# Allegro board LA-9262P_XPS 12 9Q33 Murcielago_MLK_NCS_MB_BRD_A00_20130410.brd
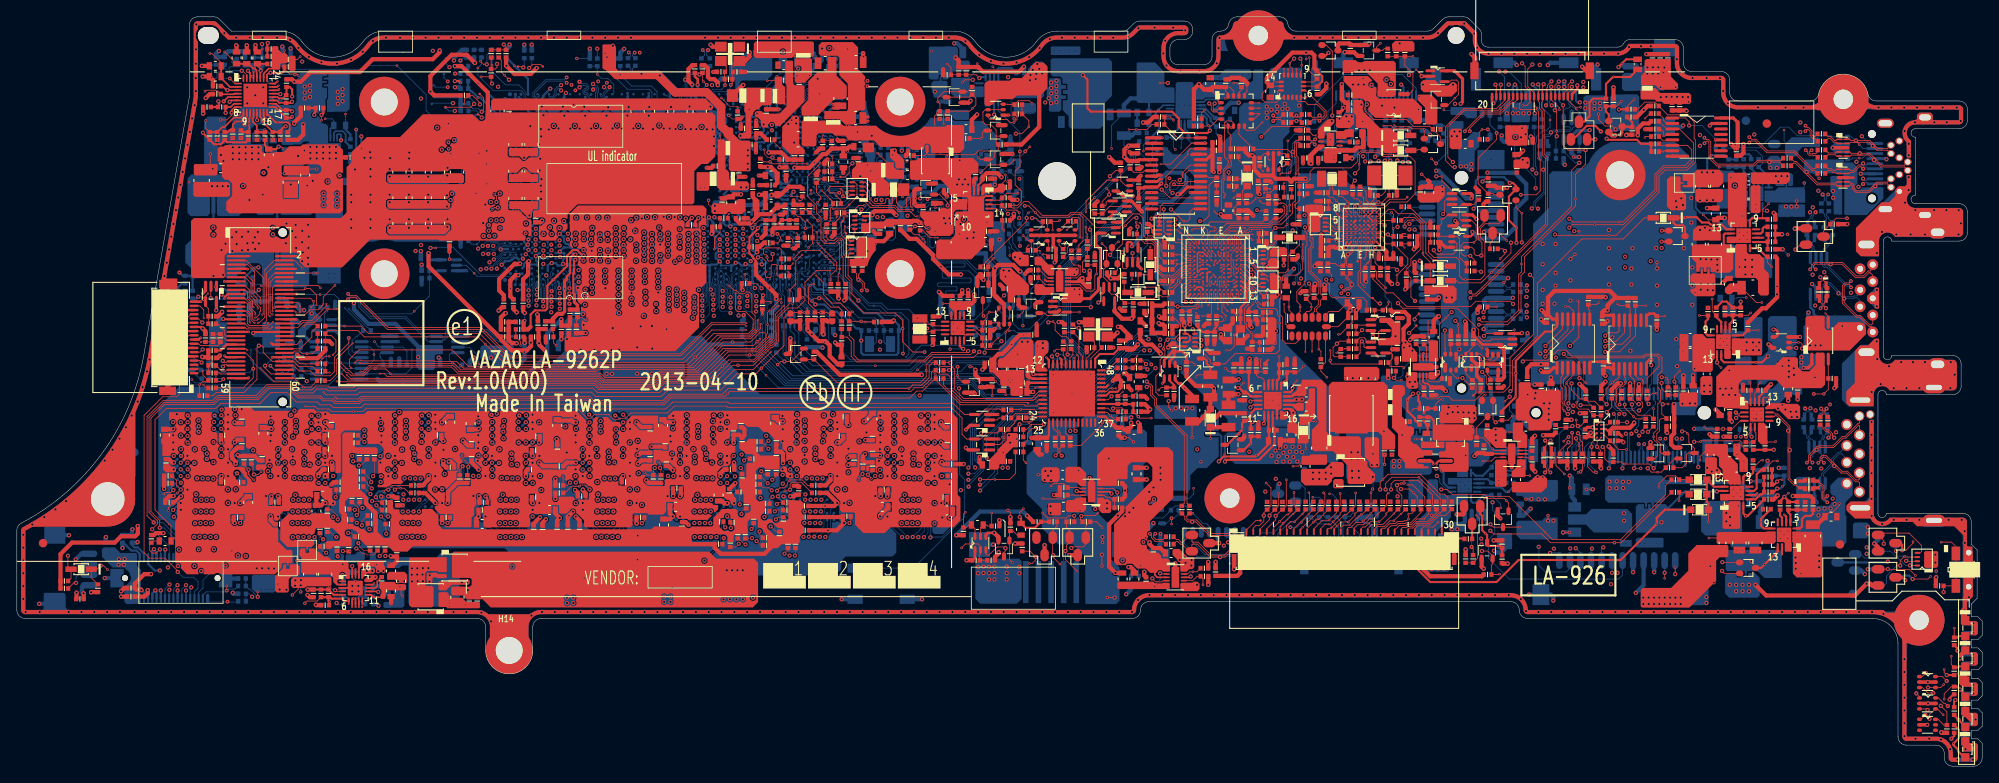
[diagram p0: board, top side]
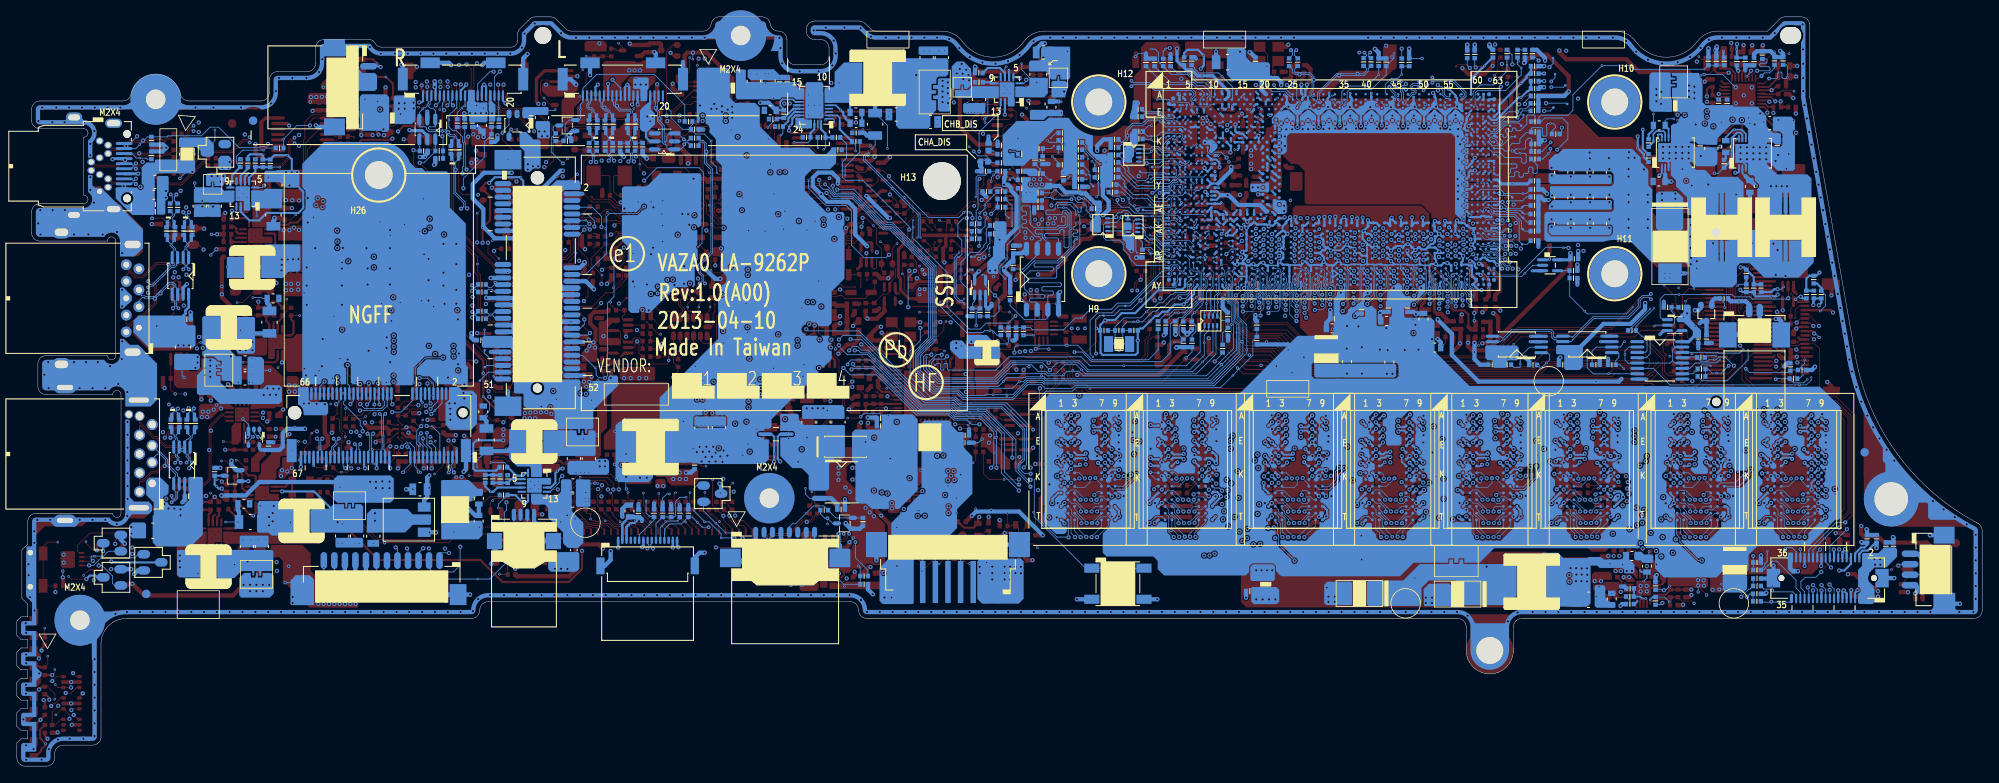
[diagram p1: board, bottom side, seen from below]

Outline 233.5 x 89.05 mm; copper layers: TOP, GND1, IN1, GND2, IN2, GND3, VCC, IN3, GND4, IN4, GND5, BOTTOM. Coordinates in mm from the lower left corner of the outline.
Outline path: 0,28 0,18.55 arc(0.29,17.84) 1,17.55 54.7,17.55 arc(55.41,17.26) 55.7,16.55 55.7,13.75 arc(58.5,10.95) 61.3,13.75 61.3,16.55 arc(61.59,17.26) 62.3,17.55 132.5,17.55 arc(133.21,17.84) 133.5,18.55 arc(133.79,19.26) 134.5,19.55 177.5,19.55 arc(178.21,19.26) 178.5,18.55 arc(178.79,17.84) 179.5,17.55 220.5,17.55 arc(222.62,16.67) 223.5,14.55 223.5,3.5 arc(223.79,2.79) 224.5,2.5 228,2.5 arc(228.71,2.21) 229,1.5 229,1 arc(229.29,0.29) 230,0 232.5,0 arc(233.21,0.29) 233.5,1 233.5,2.75 233,3.25 232.2,3.25 232.2,4.25 233,4.25 233.5,4.75 233.5,6.35 233,6.85 232.2,6.85 232.2,7.85 233,7.85 233.5,8.35 233.5,9.95 233,10.45 232.2,10.45 232.2,11.45 233,11.45 233.5,11.95 233.5,13.55 233,14.05 232.2,14.05 232.2,15.05 233,15.05 233.5,15.55 233.5,17.25 233,17.75 232.2,17.75 232.2,19.25 232.9,19.95 232.9,25.7 232.2,26.4 232.2,29.05 arc(231.91,29.76) 231.2,30.05 222.12,30.05 arc(221.62,29.55) 221.12,30.05 221.12,44.15 arc(221.62,44.65) 222.12,44.15 230,44.15 arc(230.71,44.44) 231,45.15 231,47.8 arc(230.71,48.51) 230,48.8 222.75,48.8 arc(222.25,48.3) 221.75,48.8 221.75,62.4 arc(222.25,62.9) 222.75,62.4 230.75,62.4 arc(231.46,62.69) 231.75,63.4 231.75,65.85 arc(231.46,66.56) 230.75,66.85 225.55,66.85 arc(225.05,67.35) 225.55,67.85 225.55,74.75 arc(225.05,75.25) 225.55,75.75 230.75,75.75 arc(231.46,76.04) 231.75,76.75 231.75,78.05 arc(231.46,78.76) 230.75,79.05 220.92,79.05 arc(220.29,79.28) 219.94,79.85 arc(217,82.25) 214.06,79.85 arc(213.71,79.28) 213.08,79.05 204.5,79.05 arc(203.79,79.34) 203.5,80.05 203.5,81.55 arc(203.21,82.26) 202.5,82.55 199,82.55 arc(198.29,82.84) 198,83.55 198,85.35 arc(197.71,86.06) 197,86.35 191.64,86.35 arc(191.21,86.23) 190.92,85.9 arc(190.62,85.57) 190.2,85.45 174.8,85.45 arc(174.23,85.68) 174,86.25 174,87.02 arc(173.94,87.32) 173.77,87.58 172.59,88.76 arc(172.27,88.97) 171.89,89.05 170.11,89.05 arc(169.73,88.97) 169.41,88.76 168.29,87.64 arc(167.97,87.43) 167.59,87.35 152,87.35 arc(151.35,87.59) 151.01,88.2 arc(150.67,88.81) 150.02,89.05 144.98,89.05 arc(144.33,88.81) 143.99,88.2 arc(143.65,87.59) 143,87.35 arc(142.29,87.06) 142,86.35 142,84.35 arc(141.71,83.64) 141,83.35 138,83.35 arc(137.29,83.64) 137,84.35 137,85.35 arc(137.29,86.06) 138,86.35 138.7,86.35 arc(139.41,86.64) 139.7,87.35 139.7,87.55 arc(139.41,88.26) 138.7,88.55 133.41,88.55 arc(133.03,88.47) 132.71,88.26 132.09,87.64 arc(131.77,87.43) 131.39,87.35 123.57,87.35 arc(122.21,87.02) 121.14,86.11 arc(117.5,84.25) 113.86,86.11 arc(112.79,87.02) 111.43,87.35 43.57,87.35 arc(42.21,87.02) 41.14,86.11 arc(37.5,84.25) 33.86,86.11 arc(32.79,87.02) 31.43,87.35 25.5,87.35 24.09,88.76 arc(23.77,88.97) 23.39,89.05 21.5,89.05 arc(20.79,88.76) 20.5,88.05 20.5,79.55 15.07,48.8 arc(10.11,37.15) 0.53,28.88 arc(0.14,28.52) 0,28

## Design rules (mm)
constraint set DEFAULT: min track width 0.102
net group BUS_RTC: nets PCH_RTCRST# PCH_SRTCRST#
net group BUS_SPI-CLK-15: nets PCH_SPI_CLK SPI_CLK_ROM
net group DIFFPAIR0: nets CLK_PCIE2 CLK_PCIE2#
net group DP-BQTMAN: nets BATMAN_CLK BATMAN_DATA
net group DP_ALS-SMB: nets ALS_SMBCLK ALS_SMBDATA
net group DP_SML0: nets SML0CLK SML0DATA
net group EDP_AUXP_C: nets EDP_AUXN_C EDP_AUXP_C
net group EDP_TXN_P1_C: nets EDP_TXN_P1_C EDP_TXP_P1_C
net group EDP_TXP_P0_C: nets EDP_TXN_P0_C EDP_TXP_P0_C
net group H_CPU_SVIDALRT#: nets H_CPU_SVIDALRT# VR_SVID_ALRT#
net group H_CPU_SVIDCLK: nets H_CPU_SVIDCLK VR_SVID_CLK
net group H_CPU_SVIDDAT: nets H_CPU_SVIDDAT VR_SVID_DAT
net group PCH_DP_AUXN: nets PCH_DP_AUXN PCH_DP_AUXN_C
net group PCH_DP_AUXP: nets PCH_DP_AUXP PCH_DP_AUXP_C
net group PCIE_PTX_DRX_N4: nets PCIE_PTX_DRX_N4 PCIE_PTX_DRX_N4_C
net group PCIE_PTX_DRX_P4: nets PCIE_PTX_DRX_P4 PCIE_PTX_DRX_P4_C
net group SATA_PRX_DTX_N0: nets SATA_PRX_DTX_N0 SATA_PRX_DTX_N0_C
net group SATA_PRX_DTX_P0: nets SATA_PRX_DTX_P0 SATA_PRX_DTX_P0_C
net group SATA_PTX_DRX_N0: nets SATA_PTX_DRX_N0 SATA_PTX_DRX_N0_C
net group SATA_PTX_DRX_P0: nets SATA_PTX_DRX_P0 SATA_PTX_DRX_P0_C
net group SPACING-15: nets PCH_RTCX1 PCH_RTCX2
net group +1.8VS: nets +1.8VS SDIO_RST# SDIO_WAKE#_Q
net group BUS_ASYNCHRONOUS: nets H_CATERR# H_DRAMRST# H_PECI H_PROCHOT# H_PROCHOT#_R H_THERMTRIP# H_THERMTRIP#_R PCH_PLTRST# VCCSTPG_MCP
net group BUS_CLK: nets CLK_LPC_DEBUG CLK_PCI_LPC CLK_PCI_TPM CLKOUT_LPC0 CLKOUT_LPC1
net group BUS_DDRA_CTL: nets M_ODT0
net group BUS_DDRB_CTL: nets M_ODT2
net group BUS_I2C: nets I2C0_SCK I2C0_SDA I2C1_SCK I2C1_SDA SENSOR_I2C_SCL SENSOR_I2C_SDA
net group BUS_IHDA-CLK: nets HDA_BIT_CLK HDA_BITCLK_AUDIO HDA_BITCLK_AUDIO_C HDA_BITCLK_DSP
net group BUS_IHDA-DATA: nets HDA_RST# HDA_RST_AUDIO# HDA_RST_DSP# HDA_SDIN0 HDA_SDIN0_AUDIO HDA_SDIN0_DSP HDA_SDOUT HDA_SDOUT_AUDIO HDA_SDOUT_DSP HDA_SPKR HDA_SYNC HDA_SYNC_AUDIO HDA_SYNC_DSP
net group BUS_LPC: nets LPC_AD0 LPC_AD1 LPC_AD2 LPC_AD3 LPC_FRAME#
net group BUS_POWER-RAIL: nets +1.2V_TON BOOT_+1.2V BST_+1.05VS CHG_LGATE CHG_UGATE CPU_B+ DH_+1.2V DL_+1.2V P1 PWM1 PWM2 SKIP# SKIP#1 SKIP#2 SNUB_1.5VSP SNUB_+1.2V SNUB_+1.05V SNUB_CHG SNUB_PHASE1 SNUB_PHASE2 SW_+1.2V SW_+1.05VS
net group BUS_SPI: nets PCH_SPI_CS# PCH_SPI_IO2 PCH_SPI_IO3 PCH_SPI_SI PCH_SPI_SO SPI_IO2_ROM SPI_IO3_ROM SPI_SI_ROM SPI_SO_ROM TPM_IRQ#
net group BUS_UART1: nets UART1_CTS# UART1_CTS#_NGFF UART1_RTS# UART1_RTS#_NGFF UART1_RXD UART1_RXD_NGFF UART1_TXD UART1_TXD_NGFF
net group BUS_USB2.0: nets SW_USB20_N1 SW_USB20_P1 USB20_N1 USB20_N2_R USB20_P1 USB20_P2_R
net group BUS_USB3.0: nets USB3TN0_C USB3TN1_C USB3TP0_C USB3TP1_C
net group DP_PCH-SML: nets PCH_SMLDATA
net group I2S_BCLK_OUT: nets I2S_BCLK_OUT I2S_CLK I2S_CLK_IN I2S_SFRM_IN
net group IHDA_DATA-5_10: nets HDA_SDO
net group PCH_DP_N0: nets PCH_DP_N0
net group PCH_DP_N1: nets PCH_DP_N1
net group PCH_DP_N2: nets PCH_DP_N2
net group PCH_DP_N3: nets PCH_DP_N3
net group PCH_DP_P0: nets PCH_DP_P0
net group PCH_DP_P1: nets PCH_DP_P1
net group PCH_DP_P2: nets PCH_DP_P2
net group PCH_DP_P3: nets PCH_DP_P3
net group R_DDRA-D0: nets DDR_A_D0 DDR_A_D1 DDR_A_D2 DDR_A_D3 DDR_A_D4 DDR_A_D5 DDR_A_D6 DDR_A_D7 DDR_A_DQS0 DDR_A_DQS#0
net group R_DDRA-D1: nets DDR_A_D8 DDR_A_D9 DDR_A_D10 DDR_A_D11 DDR_A_D12 DDR_A_D13 DDR_A_D14 DDR_A_D15 DDR_A_DQS1 DDR_A_DQS#1
net group R_DDRA-D2: nets DDR_A_D16 DDR_A_D17 DDR_A_D18 DDR_A_D19 DDR_A_D20 DDR_A_D21 DDR_A_D22 DDR_A_D23 DDR_A_DQS2 DDR_A_DQS#2
net group R_DDRA-D3: nets DDR_A_D24 DDR_A_D25 DDR_A_D26 DDR_A_D27 DDR_A_D28 DDR_A_D29 DDR_A_D30 DDR_A_D31 DDR_A_DQS3 DDR_A_DQS#3
net group R_DDRA-D4: nets DDR_A_D32 DDR_A_D33 DDR_A_D34 DDR_A_D35 DDR_A_D36 DDR_A_D37 DDR_A_D38 DDR_A_D39 DDR_A_DQS4 DDR_A_DQS#4
net group R_DDRA-D5: nets DDR_A_D40 DDR_A_D41 DDR_A_D42 DDR_A_D43 DDR_A_D44 DDR_A_D45 DDR_A_D46 DDR_A_D47 DDR_A_DQS5 DDR_A_DQS#5
net group R_DDRA-D6: nets DDR_A_D48 DDR_A_D49 DDR_A_D50 DDR_A_D51 DDR_A_D52 DDR_A_D53 DDR_A_D54 DDR_A_D55 DDR_A_DQS6 DDR_A_DQS#6
net group R_DDRA-D7: nets DDR_A_D56 DDR_A_D57 DDR_A_D58 DDR_A_D59 DDR_A_D60 DDR_A_D61 DDR_A_D62 DDR_A_D63 DDR_A_DQS7 DDR_A_DQS#7
net group R_DDRB-D0: nets DDR_B_D0 DDR_B_D1 DDR_B_D2 DDR_B_D3 DDR_B_D4 DDR_B_D5 DDR_B_D6 DDR_B_D7 DDR_B_DQS0 DDR_B_DQS#0
net group R_DDRB-D1: nets DDR_B_D8 DDR_B_D9 DDR_B_D10 DDR_B_D11 DDR_B_D12 DDR_B_D13 DDR_B_D14 DDR_B_D15 DDR_B_DQS1 DDR_B_DQS#1
net group R_DDRB-D2: nets DDR_B_D16 DDR_B_D17 DDR_B_D18 DDR_B_D19 DDR_B_D20 DDR_B_D21 DDR_B_D22 DDR_B_D23 DDR_B_DQS2 DDR_B_DQS#2
net group R_DDRB-D3: nets DDR_B_D24 DDR_B_D25 DDR_B_D26 DDR_B_D27 DDR_B_D28 DDR_B_D29 DDR_B_D30 DDR_B_D31 DDR_B_DQS3 DDR_B_DQS#3
net group R_DDRB-D4: nets DDR_B_D32 DDR_B_D33 DDR_B_D34 DDR_B_D35 DDR_B_D36 DDR_B_D37 DDR_B_D38 DDR_B_D39 DDR_B_DQS4 DDR_B_DQS#4
net group R_DDRB-D5: nets DDR_B_D40 DDR_B_D41 DDR_B_D42 DDR_B_D43 DDR_B_D44 DDR_B_D45 DDR_B_D46 DDR_B_D47 DDR_B_DQS5 DDR_B_DQS#5
net group R_DDRB-D6: nets DDR_B_D48 DDR_B_D49 DDR_B_D50 DDR_B_D51 DDR_B_D52 DDR_B_D53 DDR_B_D54 DDR_B_D55 DDR_B_DQS6 DDR_B_DQS#6
net group R_DDRB-D7: nets DDR_B_D56 DDR_B_D57 DDR_B_D58 DDR_B_D59 DDR_B_D60 DDR_B_D61 DDR_B_D62 DDR_B_D63 DDR_B_DQS7 DDR_B_DQS#7
nets with their own width: min track width 0.254; nets +VCCIO_OUT AOAC_THERMAL ECAGND LP# SATA_RCOMP VCCSENSE VCCSENSE_R VCIN0_PH VSSSENSE
nets with their own width: min track width 0.305; nets PCH_OPIRCOMP PCIE_RCOMP PROC_OPI_COMP
nets with their own width: min track width 0.381; nets +3VS_CAM +V1.05S_ASATA3PLL CFG_RCOMP SM_RCOMP0 SM_RCOMP1 SM_RCOMP2
nets with their own width: min track width 0.508; nets 1.2_PGND +0.6VSP +1.2V_B+ +1.2V_FB +1.2VP +1.2VS_DVDD +1.05VA +1.05VS +1.5VS +1.05VS_B+ +1.5VS_D +1.05VS_VCCST +1.05VS_XDP +1.05VSP +1.5VSP +3V_D +3V_PCH +3V_PCH_DSW +3VALW +3VALW_EC +3VLP +3VNS_PWR +3VS +3VS_AUDIO +5VS +5VS_AUDIO +5VS_KBL +EC_VCCA +EDP_COM +INV_PWR_SRC +LCDVDD +LCDVDD_R +PCH_VCCDSW +RTC_VCCSUS +RTCBATT +RTCVCC +V1.05A_AOSCSUS +V1.05S_APLLOPI +V1.05S_AUSB3PLL +V1.05S_AXCK_DCB +V1.05S_AXCK_LCPLL +V18R +VCC_CORE +VCCIOA_OUT +VCCP_D +VCHGR +VREFCA +VREFDQ_A +VREFDQ_B +VS_LPSS_SDIO B+ GND N88620271 N90173610 V_DDR_REF_CA V_DDR_REFA_R V_DDR_REFB_R VCC
nets with their own width: min track width 1.016; nets +3.3VDX_SSD
nets with their own width: min track width 2.032; nets +5V_USB_P0 +5V_USB_P1

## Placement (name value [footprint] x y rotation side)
C265  -  [C_0402]  212.63 32.09 0 bottom
C276  -  [C_0402]  136.38 51.4 0 top
C277  -  [C_0402]  136.38 52.29 0 top
C278  -  [C_0402]  148.98 51.27 180 top
C279  -  [C_0402]  148.98 52.16 180 top
C280  -  [C_0402]  133.97 54.06 0 top
C281  -  [C_0402]  133.97 54.95 0 top
C282  -  [C_0402]  144.46 53.17 0 top
C283  -  [C_0402]  147.68 49.49 0 top
C285  -  [C_0402]  139.32 54.07 270 top
C286  -  [C_0402]  145.39 54.06 180 top
C293  -  [C_0603]  143.95 65.3 90 top
C303  -  [C_1206]  216.03 27.98 0 bottom
C352  -  [C_0402]  118.12 56.73 180 top
C355  -  [C_0402]  121.36 58.06 180 top
C612  -  [C_0402]  159.07 79.77 180 top
C613  -  [C_0402]  163.89 85.27 270 top
C617  -  [C_0402]  178.21 71.46 270 top
C621  -  [C_0402]  214.26 40.59 90 top
C623  -  [C_0402]  215.15 40.59 90 top
C655  -  [C_0402]  142.87 71.22 90 top
C656  -  [C_0402]  32.53 83.31 90 bottom
C712  -  [C_0603]  182.26 44.07 90 top
C713  -  [C_0402]  198 44.12 90 top
C715  -  [C_0402]  181.12 44.44 90 top
C716  -  [C_0603]  199.16 43.81 90 top
C719  -  [C_0603]  167.81 67.48 90 top
C720  -  [C_0402]  166.73 67.78 90 top
C721  -  [C_0402]  167.56 56.38 270 top
C722  -  [C_0402]  177.92 50.63 0 bottom
C962  -  [C_0603]  202.37 43.08 270 top
C963  -  [C_0402]  203.51 42.84 270 top
C964  -  [C_0402]  154.93 48.36 270 top
C965  -  [C_0603]  158.07 55.05 0 top
C966  -  [C_0402]  158.19 53.28 0 top
C968  -  [C_0603]  150.81 55.65 90 top
C969  -  [C_0603]  141.79 80.42 90 top
C970  -  [C_0402]  143.62 80.7 90 top
C974  -  [C_0402]  145.5 80.7 90 top
C976  -  [C_0402]  155.84 61.56 180 top
C977  -  [C_0402]  162.72 60.32 180 top
C978  -  [C_0402]  155.84 60.67 180 top
C979  -  [C_0402]  163.55 60.3 0 top
C1059  -  [C_0603]  178.63 28.41 90 bottom
C1060  -  [C_0402]  163.6 73.14 90 bottom
C1061  -  [C_0402]  165.5 73.14 90 bottom
C1062  -  [C_0402]  162.71 73.14 90 bottom
C1063  -  [C_0402]  164.61 73.14 90 bottom
C1064  -  [C_0402]  160.93 73.14 90 bottom
C1065  -  [C_0402]  160.04 73.14 90 bottom
C1078  -  [C_0402]  163.17 30.52 90 top
C1098  -  [C_0402]  13.11 21.17 0 top
C1099  -  [C_0402]  11.43 26.59 270 bottom
C1100  -  [C_0402]  13.09 20.15 0 top
C1101  -  [C_0402]  13.68 27.47 270 bottom
C1102  -  [C_0402]  7.04 19.88 0 top
C1107  -  [C_0402]  214.4 66.87 270 bottom
C1108  -  [C_0402]  215.28 66.87 270 bottom
C1109  -  [C_1206]  213.76 51.12 270 bottom
C1110  -  [C_0402]  213.75 53.11 180 bottom
C1116  -  [C_0402]  136.36 54.06 0 top
C1117  -  [C_0402]  149.61 65.1 90 top
C1118  -  [C_0402]  151.57 61.14 270 top
C1122  -  [C_0402]  228.91 21.42 180 top
C1123  -  [C_0402]  27.22 20.49 180 bottom
C1124  -  [C_0402]  27.2 22.3 180 bottom
C1125  -  [C_0402]  27.2 24.21 180 bottom
C1134  -  [C_0402]  159.65 29.59 90 bottom
C1135  -  [C_0402]  133.28 68.72 90 top
C1136  -  [C_0402]  133.15 71.92 270 top
C1137  -  [C_0402]  142.06 74.13 0 top
C1138  -  [C_0402]  142.06 73.19 0 top
C1139  -  [C_0402]  133.28 67.48 270 top
C1140  -  [C_0402]  133.19 73.74 270 top
C1142  -  [C_0402]  177.11 75.1 270 bottom
C1143  -  [C_0603]  178.24 76.86 270 bottom
C1145  -  [C_0402]  179.38 76.87 270 bottom
C1146  -  [C_0402]  10.54 26.59 270 bottom
C1148  -  [C_0603]  148.91 80.9 270 top
C1149  -  [C_0402]  154.48 80.76 270 top
C1152  -  [C_0402]  152.33 65.32 270 top
C1153  -  [C_0603]  178.61 32.54 270 bottom
C1158  -  [C_0402]  179.18 74.13 0 top
C1159  -  [C_0603]  178.11 74.07 270 top
C1160  -  [C_0402]  176.46 25.06 270 top
C1161  -  [C_0402]  135.03 25.01 90 top
C1162  -  [C_0603]  137.85 25.32 180 top
C1163  -  [C_0402]  140.63 23.52 0 top
C1172  -  [C_0603]  210.46 45.57 270 top
C1173  -  [C_0402]  211.58 45.15 270 top
C1174  -  [C_0402]  166.83 30.52 90 top
C1175  -  [C_0402]  165.92 30.52 90 top
C1176  -  [C_0402]  165 30.52 90 top
C1177  -  [C_0402]  164.09 30.52 90 top
C1178  -  [C_0402]  170.49 30.54 90 top
C1179  -  [C_0402]  169.57 30.54 90 top
C1180  -  [C_0402]  168.66 30.52 90 top
C1181  -  [C_0402]  167.75 30.52 90 top
C1182  -  [C_0402]  158.6 30.52 90 top
C1183  -  [C_0402]  157.69 30.52 90 top
C1184  -  [C_0402]  156.77 30.52 90 top
C1185  -  [C_0402]  155.86 30.52 90 top
C1186  -  [C_0402]  151.29 30.49 90 top
C1187  -  [C_0402]  150.37 30.49 90 top
C1188  -  [C_0402]  149.46 30.49 90 top
C1189  -  [C_0402]  148.54 30.49 90 top
C1190  -  [C_0402]  154.94 30.52 90 top
C1191  -  [C_0402]  154.03 30.52 90 top
C1192  -  [C_0402]  153.12 30.52 90 top
C1193  -  [C_0402]  152.2 30.49 90 top
C1194  -  [C_0402]  162.26 30.52 90 top
C1195  -  [C_0402]  161.35 30.52 90 top
C1196  -  [C_0402]  160.43 30.52 90 top
C1197  -  [C_0402]  159.52 30.52 90 top
C1199  -  [C_0402]  127.31 56.97 90 top
C1200  -  [C_0402]  157.06 76.78 90 top
C1202  -  [C_0402]  180.03 37.48 90 top
C1203  -  [C_0402]  174.31 37.22 90 top
C1204  -  [C_0402]  163.03 67.83 0 top
C1205  -  [C_0402]  161.7 67.83 180 top
C1209  -  [C_0603]  112.06 75.69 0 top
C1212  -  [C_0402]  124.85 32.22 180 top
C1213  -  [C_0402]  130.41 33.62 0 top
C1214  -  [C_0402]  124.85 33.11 180 top
C1215  -  [C_0402]  179.45 45.35 90 top
C1219  -  [C_0402]  174.7 39.59 90 top
C1225  -  [C_0402]  142.42 22.62 90 top
C1227  -  [C_0402]  106.57 72.57 180 top
C1228  -  [C_0402]  113.9 70.75 270 top
C1230  -  [C_0402]  173.81 74.49 0 top
C1231  -  [C_0603]  171.37 73.96 0 top
C1237  -  [C_0402]  35.74 50.52 0 top
C1240  -  [C_0603]  109.05 65.49 90 top
C1241  -  [C_0402]  114.76 69.81 0 top
C1242  -  [C_0402]  117.08 68.8 0 top
C1243  -  [C_0402]  111.07 68.41 180 top
C1244  -  [C_0402]  117.08 67.55 0 top
C1246  -  [C_0402]  167.94 62.26 0 top
C1248  -  [C_0402]  167.19 50.13 90 top
C1254  -  [C_0402]  168.08 45 270 top
C1256  -  [C_0402]  164.85 48.41 180 top
C1257  -  [C_0402]  166.24 50.18 90 top
C1259  -  [C_0402]  175.97 45.89 270 top
C1260  -  [C_0402]  173.93 45.89 270 top
C1261  -  [C_0402]  164.03 50.46 270 top
C1262  -  [C_0402]  164.03 52.34 90 top
C1278  -  [C_0402]  121.36 58.95 180 top
C1279  -  [C_0402]  12.55 26.56 90 bottom
C1280  -  [C_0402]  134.17 22.44 270 top
C1281  -  [C_0402]  140.65 22.57 0 top
C1282  -  [C_0402]  22.8 47 90 bottom
C1283  -  [C_0402]  189.3 39.56 0 top
C1284  -  [C_0402]  186.33 39.1 90 top
C1285  -  [C_0402]  188.36 53.48 270 top
C1286  -  [C_0402]  188.49 47.1 90 top
C1287  -  [C_0402]  181.76 53.61 270 top
C1288  -  [C_0402]  181.76 46.85 90 top
C1289  -  [C_0402]  203.6 37.58 90 bottom
C1292  -  [C_0402]  180.02 36.61 270 top
C1294  -  [C_0402]  111.12 54.97 90 top
C1295  -  [C_0402]  108.85 52.53 90 top
C1296  -  [C_0402]  108.86 51.63 270 top
C1297  -  [C_0402]  158.39 74.18 0 top
C1298  -  [C_0402]  155.53 72.24 180 top
C1299  -  [C_0402]  153.73 72.29 180 top
C1300  -  [C_0402]  128.07 59.58 90 top
CA1  -  [C_0603]  132.01 39.97 0 top
CA2  -  [C_0603]  132.14 49.56 90 top
CA3  -  [C_0603]  121.22 39.01 270 top
CA4  -  [C_0402]  130.99 49.67 90 top
CA5  -  [C_0402]  122.36 39.03 270 top
CA6  -  [C_0402]  130.92 40.22 270 top
CA7  -  [C_0603]  130.82 46.19 0 top
CA8  -  [C_0603]  120.01 44.48 180 top
CA9  -  [C_0603]  116.11 35.8 180 top
CA10  -  [C_0402]  120.15 45.55 180 top
CA11  -  [C_0402]  131.12 45.11 0 top
CA12  -  [C_0402]  117.1 36.22 0 top
CA13  -  [C_0402]  130.8 43.98 270 top
CA14  -  [C_0402]  132.63 43.97 0 top
CA15  -  [C_0402]  132.65 43.01 0 top
CA16  -  [C_0402]  128.02 49.75 180 top
CA17  -  [C_0402]  128.89 49.75 0 top
CA18  -  [C_0402]  119.37 47.73 270 top
CA19  -  [C_0603]  118.29 47.9 270 top
CA20  -  [C_0603]  117.02 47.9 270 top
CA21  -  [C_0603]  133.29 44.98 90 top
CA22  -  [C_0603]  133.03 35.46 270 top
CC160  -  [C_0603]  65.73 49.75 180 bottom
CC161  -  [C_0603]  66.36 52.41 90 bottom
CC162  -  [C_0603]  75.48 48.79 270 bottom
CC163  -  [C_0603]  70.05 52.92 0 bottom
CC164  -  [C_0603]  76.52 52.03 0 bottom
CC165  -  [C_0603]  70.43 48.73 270 bottom
CC233  -  [C_0402]  73.73 54.7 270 bottom
CC234  -  [C_0402]  68.27 54.9 270 bottom
CC238  -  [C_0402]  70.56 54.9 270 bottom
CC239  -  [C_0402]  76.52 53.17 0 bottom
CC240  -  [C_0402]  48.91 60.29 180 bottom
CD1  -  [C_0402]  18.55 31.33 180 top
CD2  -  [C_0402]  31.12 31.33 180 top
CD3  -  [C_0402]  26.74 38.77 270 top
CD4  -  [C_0402]  36.56 35.27 0 top
CD5  -  [C_0402]  26.68 29.55 180 top
CD14  -  [C_0402]  26.73 41.69 270 top
CD15  -  [C_0402]  25.15 39.33 180 top
CD16  -  [C_0402]  25.15 33.74 180 top
CD17  -  [C_0402]  37.47 39.33 180 top
CD18  -  [C_0402]  37.47 37.68 180 top
CD19  -  [C_0402]  37.4 41.31 270 top
CD20  -  [C_0603]  27.49 30.63 90 top
CD21  -  [C_0603]  37.05 32.14 180 top
CD22  -  [C_B2]  29.39 24.7 90 bottom
CD23  -  [C_0402]  49.37 47.71 0 bottom
CD24  -  [C_0402]  45.19 31.92 270 top
CD25  -  [C_0402]  55.89 31.33 180 top
CD26  -  [C_0402]  51.04 35.52 0 top
CD27  -  [C_0402]  64.9 35.65 180 top
CD28  -  [C_0402]  51.45 29.55 180 top
CD37  -  [C_0402]  61.6 35.27 180 top
CD38  -  [C_0402]  54.03 37.25 270 top
CD39  -  [C_0402]  55.76 30.44 180 top
CD40  -  [C_0402]  62.11 37.55 180 top
CD41  -  [C_0402]  61.2 39.2 0 top
CD42  -  [C_0402]  62.11 31.97 180 top
CD43  -  [C_0603]  56 28.79 180 top
CD44  -  [C_0603]  62.58 30.44 0 top
CD45  -  [C_0402]  78.87 32.98 180 top
CD46  -  [C_0402]  67.57 32.09 180 top
CD47  -  [C_0402]  75.24 37.25 270 top
CD48  -  [C_0402]  84.31 35.27 0 top
CD49  -  [C_0402]  74.56 29.55 180 top
CD58  -  [C_0402]  77.03 38.77 270 top
CD59  -  [C_0402]  77.15 36.61 270 top
CD60  -  [C_0402]  75.24 39.38 90 top
CD61  -  [C_0402]  86.04 41.19 270 top
CD62  -  [C_0402]  85.15 40.3 270 top
CD63  -  [C_0402]  84.64 32.02 90 top
CD64  -  [C_0603]  83.37 32.92 270 top
CD65  -  [C_0603]  78.99 30.82 180 top
CD66  -  [C_B2]  77.92 49.85 90 bottom
CD67  -  [C_0402]  57.75 47.71 0 bottom
CD68  -  [C_0402]  92.89 32.27 90 top
CD69  -  [C_0402]  103.51 32.85 180 top
CD70  -  [C_0402]  99.47 36.82 270 top
CD71  -  [C_0402]  111.51 35.9 180 top
CD72  -  [C_0402]  99.07 29.68 180 top
CD81  -  [C_0402]  97.26 39.2 0 top
CD82  -  [C_0402]  97.71 41.54 0 top
CD83  -  [C_0402]  101.66 37.88 270 top
CD84  -  [C_0402]  110.55 41.19 270 top
CD85  -  [C_0402]  110.55 38.9 270 top
CD86  -  [C_0402]  109.58 31.97 0 top
CD87  -  [C_0603]  102.1 30.82 0 top
CD88  -  [C_0603]  109.79 30.39 0 top
CD89  -  [C_0402]  60.21 51.9 180 top
CD90  -  [C_0402]  58.43 51.9 180 top
CD91  -  [C_0402]  66.61 54.27 270 top
CD92  -  [C_0402]  63.68 52.87 270 top
CD93  -  [C_0402]  79.05 28.08 90 top
CD94  -  [C_0402]  93.2 28.03 0 top
CD95  -  [C_0402]  93.12 30.92 0 top
CD96  -  [C_0402]  66.86 27.7 90 top
CD97  -  [C_0402]  90.23 36.46 90 top
CD98  -  [C_0402]  86.16 38.11 90 top
CD101  -  [C_0603]  35.59 29.62 90 top
CD102  -  [C_0402]  38.87 33.74 180 top
CD103  -  [C_0402]  64.19 27.7 90 top
CD104  -  [C_0402]  31.68 28.77 180 top
CD105  -  [C_0402]  45.14 25.82 270 top
CD106  -  [C_0402]  65.46 27.7 90 top
CD107  -  [C_0402]  61.4 27.7 90 top
CD110  -  [C_0603]  76.89 27.97 90 top
CD111  -  [C_0402]  72.78 33.74 180 top
CD112  -  [C_0402]  101.66 39.66 270 top
CD113  -  [C_0603]  101.66 40.54 90 top
CD114  -  [C_0603]  90.1 40.03 90 top
CD115  -  [C_0402]  90.24 39.13 270 top
CD116  -  [C_0402]  64.21 37.22 90 top
CD117  -  [C_0603]  76.77 39.78 90 top
CD118  -  [C_0603]  64.21 39.78 90 top
CD119  -  [C_0402]  49.51 39.33 0 top
CD120  -  [C_0402]  54.03 39.03 270 top
CD121  -  [C_0603]  51.49 40.16 90 top
CD122  -  [C_0603]  53.91 41.43 270 top
CD123  -  [C_0402]  29.15 37.25 270 top
CD124  -  [C_0402]  17.71 35.57 90 top
CD125  -  [C_0603]  29.29 38.84 90 top
CD126  -  [C_0603]  17.58 38.63 90 top
CH1  -  [C_0402]  22.75 48.51 0 top
CH2  -  [C_0402]  103.88 51.78 0 bottom
CH3  -  [C_0402]  101.24 51.78 180 bottom
CH4  -  [C_0402]  93.05 53.01 90 top
CH5  -  [C_0402]  95.72 53.92 270 top
CH6  -  [C_0402]  115.09 60.95 90 bottom
CH11  -  [C_0402]  73.5 84.15 270 bottom
CH16  -  [C_0402]  72.61 84.15 270 bottom
CH23  -  [C_0402]  84.11 82.51 180 top
CH24  -  [C_0402]  85.1 82.51 0 top
CH39  -  [C_0402]  91.4 71.16 270 top
CH40  -  [C_0402]  93.24 73 270 top
CH41  -  [C_0402]  92.37 73 270 top
CH47  -  [C_0402]  90.06 69.05 180 top
CH82  -  [C_0402]  92.65 64.89 270 top
CH83  -  [C_0402]  90.87 64.89 270 top
CH84  -  [C_0402]  91.76 64.89 270 top
CH85  -  [C_0402]  87.03 61.73 0 top
CH95  -  [C_0402]  32.76 51.21 270 bottom
CH1202  -  [C_0402]  156.61 68.16 0 top
CH1203  -  [C_0402]  155.77 68.16 180 top
CH1204  -  [C_0603]  84.88 66.26 90 top
CH1205  -  [C_0402]  83.8 66.56 90 top
CH1206  -  [C_0402]  92.29 65.8 90 top
CH1207  -  [C_0402]  89.97 64.88 270 top
CH1208  -  [C_0805]  97.86 80.18 270 top
CH1209  -  [C_0805]  96.9 83.54 180 top
CH1210  -  [C_0805]  98.8 77.03 0 top
CH1211  -  [C_0805]  98.85 83.67 0 top
CH1212  -  [C_A1]  83.95 69.81 180 top
CH1213  -  [C_0402]  83.66 71.32 180 top
CH1214  -  [C_0402]  114.75 63.56 0 top
CH1215  -  [C_0402]  87.43 68.08 90 top
CH1216  -  [C_0402]  89.03 77.14 90 top
CH1217  -  [C_0603]  91.83 83.31 180 top
CH1218  -  [C_0402]  83.55 64.1 180 top
CH1220  -  [C_0603]  90.34 67.91 180 top
CH1222  -  [C_0402]  91.29 66.71 270 top
CH1223  -  [C_0603]  90.34 66.51 180 top
CH1224  -  [C_0402]  102.55 64.17 270 top
CH1225  -  [C_0603]  90.34 70.19 180 top
CH1226  -  [C_0402]  87.85 75.2 90 top
CH1227  -  [C_0402]  98.19 73.41 90 top
CH1228  -  [C_A1]  87.48 79.69 180 top
CH1229  -  [C_0402]  86.92 75.78 180 top
CH1230  -  [C_1206]  88.35 83.65 0 bottom
CH1231  -  [C_0402]  86.35 83.31 90 bottom
CH1232  -  [C_0402]  99.97 71.36 90 top
CH1233  -  [C_0402]  85.45 65.11 0 top
CH1234  -  [C_0402]  86.89 73.88 0 top
CH1235  -  [C_0402]  85.81 70.95 270 top
CH1236  -  [C_0402]  33.73 51.22 270 bottom
CH1237  -  [C_0402]  82.34 84.11 270 bottom
CH1238  -  [C_0402]  81.33 84.11 270 bottom
CH1239  -  [C_0603]  114.38 62.29 0 top
CH1240  -  [C_A1]  102.92 68.52 0 top
CH1241  -  [C_0402]  58.13 84.21 90 bottom
CLRP1  -  [SHORTPADS]  91.91 53.34 90 top
CLRP2  -  [SHORTPADS]  96.86 53.34 270 top
CLRP3  -  [SHORTPADS]  97.97 48.22 90 top
CS42  -  [C_0402]  178.7 53.17 180 bottom
CS43  -  [C_0402]  178.7 54.06 180 bottom
CS53  -  [C_0402]  178.7 56.35 180 bottom
CS54  -  [C_0402]  178.7 57.24 180 bottom
CV1  -  [C_0603]  217.93 67.91 180 bottom
CV2  -  [C_0402]  217.49 65.87 180 bottom
CV3  -  [C_0402]  214.85 75.15 180 top
CV4  -  [C_0402]  214.87 74.26 180 top
CV5  -  [C_0402]  214.87 73.24 180 top
CV6  -  [C_0402]  214.85 71.34 180 top
CV7  -  [C_0402]  214.87 72.35 180 top
CV8  -  [C_0402]  195.07 77.56 180 top
CV9  -  [C_0402]  214.85 70.45 180 top
CV10  -  [C_0402]  195.09 74.83 180 top
CV11  -  [C_0402]  210.78 72.25 180 top
CV12  -  [C_0402]  210.78 71.36 180 top
CV13  -  [C_0402]  204.3 73.47 270 top
CV14  -  [C_0402]  217.49 66.76 180 bottom
CV15  -  [C_0805]  217.95 69.43 180 bottom
D72  -  [BAT54CW-7-F_SOT323-3]  169.12 73.93 270 top
D73  -  [SDMK0340L-7-F_SOD323-2]  163.21 73.18 0 top
D74  -  [SDMK0340L-7-F_SOD323-2]  167.92 57.68 0 top
D81  -  [SDMK0340L-7-F_SOD323-2]  8.84 23.41 180 top
D84  -  [SDMK0340L-7-F_SOD323-2]  150.01 62.83 0 top
D85  -  [SDMK0340L-7-F_SOD323-2]  134.67 58.39 90 top
D92  -  [SDMK0340L-7-F_SOD323-2]  163.21 74.96 0 top
D93  -  [BAT54CW-7-F_SOT323-3]  176.21 67.91 90 top
D94  -  [SDMK0340L-7-F_SOD323-2]  167.92 59.42 0 top
D104  -  [BAT54CW-7-F_SOT323-3]  130.11 61.62 0 top
D105  -  [BAT54CW-7-F_SOT323-3]  156.96 85.05 270 top
D109  -  [RB751V-40GTE-17_SOD323-2]  146.17 71.04 270 top
D113  -  [BAT1000-7-F_SOT23-3]  210.88 72.96 270 bottom
D114  -  [SDMK0340L-7-F_SOD323-2]  134.4 56.3 180 top
D115  -  [BAT54CW-7-F_SOT323-3]  174.73 41.56 180 top
DE1  -  [PESD5V0U2BT_SOT23-3]  141.69 26.5 90 top
DE2  -  [PESD5V0U2BT_SOT23-3]  149.83 32.38 90 bottom
DPF1  -  [F_1206L150PR]  213.27 74.16 270 bottom
F1  -  [F_1812L075-24DR]  181.43 27.88 90 bottom
FD1  -  [FIDUCIAL_C40M80]  218.12 20.47 180 bottom
FD2  -  [FIDUCIAL_C40M80]  13.96 37.3 180 bottom
FD3  -  [FIDUCIAL_C40M80]  205.43 76.71 180 bottom
FD4  -  [FIDUCIAL_C40M80]  216.61 26.35 0 top
FD5  -  [FIDUCIAL_C40M80]  207.92 76.37 0 top
FD6  -  [FIDUCIAL_C40M80]  3.12 26.5 0 top
H1  -  [H_2P3]  217 79.25 0 top
H3  -  [H_4P0]  10.8 31.75 0 top
H5  -  [H_2P3]  226 17.35 0 top
H6  -  [H_2P3]  147.5 86.83 0 top
H8  -  [H_2P3]  144.1 31.85 0 top
H9  -  [H_3P2]  104.95 58.52 0 top
H10  -  [H_3P2]  43.65 78.93 0 top
H11  -  [H_3P2]  43.65 58.52 0 top
H12  -  [H_3P2]  104.95 78.93 0 top
H13  -  [H_4P5N]  123.6 69.52 0 top
H14  -  [H_3P2]  58.5 13.75 0 top
H16  -  [H_2P0X2P5N]  22.75 86.83 90 top
H17  -  [H_2P0N]  171 86.83 0 top
H26  -  [H_3P3]  190.5 70.25 0 top
JAPS  -  [E-T_6705K-Y18N-00L_18P]  21.06 46.7 270 top
JBATT1  -  [FOX_GS73091-10272-7H_9P-T]  116.87 21.88 180 bottom
JBL1  -  [ACES_50519-00401-P01_4P-T]  174.45 29.87 180 bottom
JBT1  -  [ACES_50271-00201-001_2P]  27.67 54.15 180 bottom
JDCIN1  -  [ACES_50281-00501-001_5P-T]  191.72 83.17 270 bottom
JDEBUG  -  [ACES_50281-0120N-001_12P]  183.28 24.44 180 bottom
JFAN1  -  [ACES_50281-0040N-001_4P]  8.57 25.25 90 bottom
JIOL1  -  [E-T_1001-F36E-03R_36P]  14.1 19.92 0 bottom
JKB1  -  [ACES_50699-03041-001_30P-T]  146.1 27.85 0 top
JLVDS1  -  [ACES_50406-02071-001_20P]  166.25 79.69 180 bottom
JLVDS2  -  [ACES_50406-02071-001_20P]  185.24 79.69 180 bottom
JMDP1  -  [ACON_MAR2B-20K1200_20P-T]  223.66 74.3 270 bottom
JNFC1  -  [HB_A531515-SCHR21_15P-T]  162.06 26.85 180 bottom
JNGFF1  -  [LOTES_APCI0019-P001A01_67P-T]  181.25 36.72 0 bottom
JSATA1  -  [TYCO_2041119-1_52P]  175.75 69.22 270 bottom
JSNRDG  -  [ACES_50506-02041-P01_20P]  184.78 79.59 180 top
JTP1  -  [ACES_51524-00801-001_8P]  145.72 27.8 180 bottom
JUSB1  -  [TAIWI_USB014-107CRL-TW_10P-T]  217.42 33.6 270 bottom
JUSB2  -  [ACON_TARAG-9V1391_9P-T]  219 52.1 270 bottom
JXDP  -  [SAMTE_BSH-030-01-L-D-A_60P]  26.06 60.61 270 top
L43  -  [KC_FBMA-L11-160808-800LMT_2P]  143.85 50.57 90 top
L44  -  [KC_FBMA-L11-160808-800LMT_2P]  145.37 50.47 90 top
L61  -  [MURAT_LQM2MPN2R2NG0L_2P]  90.88 79.63 180 top
L62  -  [MURAT_LQM2MPN2R2NG0L_2P]  93.44 83.68 90 top
L63  -  [MURAT_LQM2MPN2R2NG0L_2P]  102.14 70.83 0 top
LA1  -  [CYNTE_PG031B-4R7MS_2P]  117.14 49.12 0 bottom
LED1  -  [LED_27-11-T1D-CP1Q1RY-3C_2P]  231.5 17.35 270 top
LED2  -  [LED_27-11-T1D-CP1Q1RY-3C_2P]  231.5 13.75 270 top
LED3  -  [LED_27-11-T1D-CP1Q1RY-3C_2P]  231.5 10.15 270 top
LED4  -  [LED_27-11-T1D-CP1Q1RY-3C_2P]  231.5 6.55 270 top
LED5  -  [LED_27-11-T1D-CP1Q1RY-3C_2P]  231.5 2.95 270 top
LH10  -  [MURAT_LQM2MPN2R2NG0L_2P]  94.32 76.14 90 top
LH11  -  [MURAT_LQM2MPN2R2NG0L_2P]  97 75.7 90 top
LH12  -  [MURAT_LQM2MPN2R2NG0L_2P]  85.27 73.44 180 top
MC94  -  [C_0402]  96.87 71.56 180 top
MC102  -  [C_0402]  93.31 66.71 270 top
MC103  -  [C_0402]  89.59 52.11 270 bottom
MC118  -  [C_0402]  95.02 70.24 270 top
MC284  -  [C_0402]  134.31 63.51 90 top
MC654  -  [C_0402]  146.11 65.11 90 top
MC1133  -  [C_0402]  182.86 72.22 0 bottom
MC1141  -  [C_0402]  142.55 68.16 270 top
MC1151  -  [C_0402]  159.06 78.83 180 top
MC1210  -  [C_0402]  185.62 73.11 180 bottom
MC1267  -  [C_0402]  62.47 27.67 90 top
MC1268  -  [C_0402]  93.2 29.6 0 top
MC1269  -  [C_0402]  61.62 65.57 270 top
MC1270  -  [C_0402]  58.48 77.3 90 top
MC1271  -  [C_0402]  40.04 72.35 180 top
MC1272  -  [C_0402]  51.4 62.78 270 top
MC1273  -  [C_0402]  86.54 20.82 0 bottom
MC1274  -  [C_0402]  136.42 73.24 180 bottom
MC1275  -  [C_0402]  152.98 36.23 270 bottom
MC1276  -  [C_0402]  107.83 68.86 180 bottom
MC1277  -  [C_0402]  116.06 73.75 0 bottom
MC1297  -  [C_0402]  15.97 26.56 90 top
MD1  -  [RCLAMP0524PATCT_SLP2510P8-10-9]  216.54 74.49 270 top
MD2  -  [RCLAMP0524PATCT_SLP2510P8-10-9]  216.54 70.94 270 top
MD50  -  [IP4223CZ6_SO6-6]  183.78 76.84 0 bottom
MD74  -  [AZ1065-06QPRDG_MSOP8]  212.91 37.93 0 bottom
MD82  -  [AZ1065-06QPRDG_MSOP8]  213.09 60.43 0 bottom
MD90  -  [IP4223CZ6_SO6-6]  155.36 73.31 90 bottom
ML9  -  [R_0603]  18.32 26.76 180 top
ML40  -  [SW_WCM2012F2S_4P]  212.06 33.88 0 top
ML45  -  [MURAT_DLW21SN670HQ2L_4P]  215.09 41.58 270 bottom
ML46  -  [MURAT_DLW21SN670HQ2L_4P]  213.2 41.58 270 bottom
ML49  -  [SW_WCM2012F2S_4P]  182.31 37.58 270 top
ML52  -  [SW_WCM2012F2S_4P]  214.96 57.2 270 top
ML53  -  [MURAT_DLW21SN670HQ2L_4P]  215.61 64.44 270 bottom
ML54  -  [MURAT_DLW21SN670HQ2L_4P]  213.58 64.44 270 bottom
ML55  -  [SW_WCM2012F2S_4P]  181.83 72.39 90 bottom
ML56  -  [MURAT_DLW21SN670HQ2L_4P]  164.63 75.44 90 bottom
ML57  -  [MURAT_DLW21SN670HQ2L_4P]  162.73 75.44 90 bottom
ML58  -  [MURAT_DLW21SN670HQ2L_4P]  160.07 75.44 90 bottom
MR226  -  [R_0402]  137.29 60.79 180 top
MR256  -  [R_0402]  95.96 70.68 0 top
MR976  -  [R_0402]  142.55 69.94 270 top
NOREF  -  []  157.6 38.46 0 top
NOREF#2  -  []  226 17.35 0 top
NOREF#3  -  []  217 79.25 0 top
NOREF#4  -  []  44.63 20.46 0 top
NOREF#5  -  []  43.65 78.93 0 top
NOREF#6  -  []  28.85 130.13 0 top
NOREF#7  -  []  144.1 31.85 0 top
NOREF#8  -  []  58.5 13.75 0 top
NOREF#9  -  []  104.95 78.93 0 top
NOREF#10  -  []  151.87 78.66 0 top
NOREF#11  -  []  43.65 58.52 0 top
NOREF#12  -  []  95.07 -22.12 0 top
NOREF#13  -  []  10.8 31.75 0 top
NOREF#14  -  []  147.5 86.83 0 top
NOREF#15  -  []  90.46 -25.84 0 top
NOREF#16  -  []  101.37 6.17 0 top
NOREF#17  -  []  104.95 58.52 0 top
NOREF#18  -  []  27.25 -11.28 180 bottom
NOREF#19  -  []  48.58 -16.48 180 bottom
NOREF#20  -  []  49.03 -11.82 180 bottom
PC101  -  [C_0402]  195.24 83.71 90 top
PC102  -  [C_0402]  196.16 83.71 90 top
PC103  -  [C_0402]  197.56 78.84 270 top
PC104  -  [C_0402]  196.65 78.84 270 top
PC105  -  [C_0402]  130.42 41.36 0 bottom
PC106  -  [C_0402]  130.41 40.42 0 bottom
PC107  -  [C_0402]  121.29 39.33 180 bottom
PC108  -  [C_0402]  121.3 38.44 180 bottom
PC109  -  [C_0402]  194.33 83.71 90 top
PC112  -  [C_0402]  141.41 51.6 270 top
PC113  -  [C_0402]  137.48 45 270 top
PC114  -  [C_0603]  119.31 28.85 270 top
PC115  -  [C_0603]  113.42 28.66 0 top
PC116  -  [C_0402]  115.41 58.45 180 top
PC202  -  [C_0402]  163.38 37.93 270 top
PC203  -  [C_0402]  162.49 37.93 270 top
PC204  -  [C_0805]  160.59 45.21 90 top
PC205  -  [C_0805]  158.86 45.21 90 top
PC206  -  [C_0402]  164.57 40.94 0 top
PC208  -  [C_0402]  169.48 42.51 180 top
PC209  -  [C_0402]  167.62 40.55 90 top
PC210  -  [C_0402]  150.88 47.71 180 top
PC211  -  [C_0402]  149.97 46.76 0 top
PC212  -  [C_0402]  151.82 46.81 90 top
PC213  -  [C_0603]  151.44 40.09 270 top
PC214  -  [C_0805]  143.96 44.2 90 top
PC216  -  [C_0402]  144.6 46.88 90 top
PC217  -  [C_0805]  152.15 39.37 90 bottom
PC218  -  [C_0603]  153.92 44.41 180 top
PC219  -  [C_0805]  150.1 39.4 90 bottom
PC220  -  [C_0402]  145.87 43.48 90 top
PC221  -  [C_0603]  153.11 36.35 270 top
PC223  -  [C_0805]  139.44 40.03 90 bottom
PC224  -  [C_0805]  137.66 40.03 90 bottom
PC225  -  [C_0805]  135.88 40.03 90 bottom
PC227  -  [C_0402]  149.68 39.93 180 top
PC228  -  [C_0603]  148.71 38.66 0 top
PC229  -  [C_0402]  146.62 39.19 90 top
PC302  -  [C_0805]  206.56 27.38 270 top
PC303  -  [C_0805]  204.65 27.38 270 top
PC304  -  [C_0402]  210.48 31.39 270 top
PC305  -  [C_0805]  204.38 25.25 90 bottom
PC306  -  [C_0805]  206.15 25.25 90 bottom
PC307  -  [C_0603]  214.84 29.65 0 top
PC308  -  [C_0402]  208.38 30.54 180 top
PC310  -  [C_0805]  199.66 50.63 180 top
PC311  -  [C_0805]  199.66 48.86 180 top
PC312  -  [C_0402]  204.81 54.5 270 top
PC313  -  [C_0805]  207.23 46.09 180 bottom
PC314  -  [C_0805]  207.23 47.97 180 bottom
PC315  -  [C_0603]  203.77 55.59 180 bottom
PC316  -  [C_0402]  200.92 53.56 90 top
PC318  -  [C_0805]  204.91 66.51 0 top
PC319  -  [C_0805]  204.91 68.29 0 top
PC320  -  [C_0402]  208.92 63.21 180 top
PC321  -  [C_0805]  199.83 61.18 90 top
PC322  -  [C_0805]  201.73 61.18 90 top
PC323  -  [C_0603]  203.42 56.57 90 top
PC324  -  [C_0402]  208.01 64.99 0 top
PC326  -  [C_0805]  168.28 31.56 180 bottom
PC327  -  [C_0805]  168.29 33.36 180 bottom
PC328  -  [C_0402]  176.96 34.59 270 bottom
PC329  -  [C_0805]  165.54 37.39 270 bottom
PC330  -  [C_0805]  167.32 37.39 270 bottom
PC331  -  [C_0603]  178.09 41.4 90 bottom
PC332  -  [C_0402]  175.22 32.22 0 bottom
PC334  -  [C_0805]  202.66 37.55 0 top
PC335  -  [C_0805]  203.49 35.74 0 top
PC336  -  [C_0402]  208.52 33.48 180 top
PC337  -  [C_0805]  193.07 28.19 270 bottom
PC338  -  [C_0805]  194.85 28.19 270 bottom
PC339  -  [C_0603]  207.23 31.18 180 bottom
PC340  -  [C_0402]  206.28 35.43 90 top
PC341  -  [C_0805]  184.75 32.91 0 bottom
PC342  -  [C_0805]  191.15 28.18 270 bottom
PC403  -  [C_0805]  119.18 80.07 270 bottom
PC404  -  [C_0402]  112.78 83.08 270 top
PC405  -  [C_0805]  110.69 84.81 0 bottom
PC407  -  [C_0603]  110.59 77.6 90 bottom
PC408  -  [C_0402]  118.73 81.28 0 bottom
PC410  -  [C_0805]  209.99 67.4 270 bottom
PC411  -  [C_0805]  211.77 67.4 270 bottom
PC412  -  [C_0402]  203.38 72.1 270 bottom
PC413  -  [C_0805]  202 69.77 270 top
PC414  -  [C_0805]  200.22 69.77 270 top
PC415  -  [C_0402]  206.94 71.21 90 bottom
PC416  -  [C_0603]  201.86 64.92 90 top
PC501  -  [C_0402]  139.21 74.74 0 bottom
PC502  -  [C_0402]  142.49 76.01 0 bottom
PC503  -  [C_0603]  133.1 77.69 0 bottom
PC504  -  [C_0603]  143.29 77.94 0 bottom
PC505  -  [C_0805]  125.41 83.35 90 bottom
PC506  -  [C_0805]  123.6 83.35 90 bottom
PC507  -  [C_0805]  125.8 76.56 180 bottom
PC508  -  [C_0805]  128.19 77.44 0 bottom
PC509  -  [C_0402]  133.33 75.26 0 bottom
PC510  -  [C_0805]  145.94 80.56 90 bottom
PC511  -  [C_0402]  141.97 80.86 90 bottom
PC512  -  [C_0402]  142.88 80.86 90 bottom
PC513  -  [C_0805]  144.19 80.58 90 bottom
PC602  -  [C_0805]  52.34 20.92 270 top
PC603  -  [C_0402]  53.75 20.08 270 top
PC604  -  [C_0402]  54.69 20.08 270 top
PC605  -  [C_0603]  40.9 24.98 0 bottom
PC606  -  [C_0805]  34.86 23.67 270 top
PC607  -  [C_0805]  36.63 23.67 270 top
PC608  -  [C_0603]  44.46 22.48 90 top
PC609  -  [C_0402]  38.81 20.97 90 bottom
PC610  -  [C_B]  60.64 20.45 0 bottom
PC611  -  [C_B]  72.3 20.52 0 bottom
PC612  -  [C_0603]  44.46 21.54 270 top
PC613  -  [C_0603]  44.01 19.15 90 bottom
PC614  -  [C_0402]  37.03 20.08 90 top
PC615  -  [C_0402]  35.25 20.99 270 top
PC616  -  [C_0402]  41.37 21.12 0 bottom
PC701  -  [C_0805]  32.18 74.27 270 bottom
PC702  -  [C_0805]  26.09 76.43 180 bottom
PC703  -  [C_0402]  31.31 78.31 90 bottom
PC704  -  [C_0402]  30.3 78.31 90 bottom
PC705  -  [C_D2]  37.09 64.96 270 bottom
PC707  -  [C_0603]  29.93 71.93 90 top
PC708  -  [C_0402]  31.99 77.97 270 top
PC709  -  [C_0402]  30.41 75.35 270 top
PC710  -  [C_0402]  33.5 74.18 270 bottom
PC711  -  [C_0402]  39.63 74.52 270 bottom
PC712  -  [C_0603]  34.26 70.95 270 top
PC713  -  [C_0603]  37.69 69.48 0 bottom
PC714  -  [C_0402]  29.76 85.23 0 top
PC715  -  [C_0603]  22.87 83.22 0 top
PC716  -  [C_0402]  31.99 78.83 90 top
PC717  -  [C_0603]  28.59 84.87 270 top
PC718  -  [C_0402]  24.35 74.23 270 bottom
PC719  -  [C_0402]  30.66 72.05 270 bottom
PC720  -  [C_0603]  27.32 84.87 270 top
PC721  -  [C_0402]  27.1 84.2 270 bottom
PC722  -  [C_0603]  23.5 71.06 0 top
PC723  -  [C_0603]  27.6 69.6 270 bottom
PC724  -  [C_0402]  32.7 83.99 180 top
PC801  -  [C_0805]  59.23 68.33 270 top
PC802  -  [C_0805]  45.45 71.45 270 top
PC803  -  [C_0805]  50.04 68.4 270 top
PC804  -  [C_0805]  47.75 68.4 270 top
PC805  -  [C_0805]  45.47 68.4 270 top
PC806  -  [C_0805]  45.43 68.38 270 bottom
PC807  -  [C_0805]  47.71 68.38 270 bottom
PC808  -  [C_0805]  50 65.33 270 bottom
PC809  -  [C_0805]  52.3 71.45 270 top
PC810  -  [C_0805]  50.04 65.35 270 top
PC811  -  [C_0805]  47.75 65.35 270 top
PC812  -  [C_0805]  45.47 65.35 270 top
PC813  -  [C_0805]  45.43 65.33 270 bottom
PC814  -  [C_0805]  47.71 65.33 270 bottom
PC815  -  [C_0805]  47.74 71.45 270 top
PC816  -  [C_0805]  47.73 71.42 270 bottom
PC817  -  [C_0805]  50.03 71.45 270 top
PC818  -  [C_0805]  50.01 71.42 270 bottom
PC819  -  [C_0805]  50.01 68.38 270 bottom
PC820  -  [C_0805]  45.44 71.42 270 bottom
PC821  -  [C_0805]  61.14 68.33 270 top
PC822  -  [C_0805]  59.23 71.56 270 top
PC823  -  [C_0805]  61.14 71.56 270 top
PC824  -  [C_0805]  59.23 74.74 270 top
PC825  -  [C_0805]  61.14 74.74 270 top
PC826  -  [C_0805]  81.13 76.96 90 top
PC827  -  [C_0805]  57.11 77.01 90 top
PC828  -  [C_0805]  76.55 76.96 90 top
PC829  -  [C_0805]  78.85 76.96 90 top
PC830  -  [C_0805]  73.75 76.96 90 top
PD103  -  [TP0610K-T1-E3_SOT23-3]  126.04 25.08 0 top
PD104  -  [TP0610K-T1-E3_SOT23-3]  122.1 25.08 0 top
PD201  -  [RB751V-40_SOD323-2]  141.8 40.29 90 top
PD202  -  [RB751V-40_SOD323-2]  152.9 40.97 270 top
PD204  -  [D_EC31QS04]  135.03 37.96 0 bottom
PD301  -  [RB751V-40TE17_SOD323-2]  200.79 34.05 270 top
PD302  -  [RB751V-40TE17_SOD323-2]  200.78 32.31 270 top
PD303  -  [RB751V-40TE17_SOD323-2]  198.88 30.48 90 top
PD305  -  [SDMK0340L-7-F_SOD323-2]  196.82 65.16 180 top
PD306  -  [BAT54CW-7-F_SOT323-3]  198.19 62.99 270 top
PD307  -  [BAT54CW-7-F_SOT323-3]  206.58 23.56 270 top
PH101  -  [R_0402]  79.7 64.33 0 top
PH701  -  [R_0402]  39.64 71.82 90 bottom
PH702  -  [R_0402]  28.02 59.02 270 bottom
PH703  -  [R_0402]  20.01 58.28 270 bottom
PJP302  -  [JUMP_43X79]  205.01 23.35 270 bottom
PJP304  -  [JUMP_43X79]  208.95 47.05 0 bottom
PJP306  -  [JUMP_43X79]  200.59 58.38 90 top
PJP308  -  [JUMP_43X79]  166.3 40.26 270 bottom
PJP310  -  [JUMP_43X79]  193.96 31.5 270 bottom
PJP401  -  [JUMP_43X39]  121.17 81.14 270 bottom
PJP402  -  [JUMP_43X39]  109.75 82.26 270 bottom
PJP403  -  [JUMP_43X39]  210.24 69.61 270 bottom
PJP404  -  [JUMP_43X39]  198.56 69.3 180 top
PJP501  -  [JUMP_43X118]  123.9 80.11 0 bottom
PJP602  -  [JUMP_43X118]  62.48 23.82 90 bottom
PJP603  -  [JUMP_43X39]  34.49 25.23 90 top
PJP604  -  [JUMP_43X39]  32.2 23.33 90 top
PJP701  -  [JUMP_43X79]  37.2 81.32 180 bottom
PL101  -  [KC_FBMA-L11-201209-221LMA30_2P]  193.71 81.39 270 top
PL102  -  [MURAT_BLM18BD102SN1D_L0603_2P]  192.56 82.8 90 top
PL103  -  [L_1812-1806]  127.03 39.08 180 bottom
PL104  -  [KC_FBMA-L11-201209-221LMA30_2P]  188.06 77.03 0 bottom
PL201  -  [KC_FBMA-L11-201209-221LMA30_2P]  164 44.16 180 top
PL202  -  [KC_FBMA-L11-201209-221LMA30_2P]  164 42.35 180 top
PL203  -  [CYNTE_PCMB063T-2R2MS_2P]  155.29 37.93 0 bottom
PL301  -  [CYNTE_PCME051E-2R2MS_2P]  212.77 23.71 180 bottom
PL302  -  [MURAT_BLM18SG700TN1D_2P]  202.65 25.92 90 top
PL303  -  [CYNTE_PCME051E-2R2MS_2P]  206.27 52.13 0 bottom
PL304  -  [MURAT_BLM18SG700TN1D_2P]  200.77 46 90 top
PL305  -  [CYNTE_PCME051E-2R2MS_2P]  207.58 59.27 180 bottom
PL306  -  [MURAT_BLM18SG700TN1D_2P]  206.36 69.95 180 top
PL307  -  [CYNTE_PCME051E-2R2MS_2P]  174.06 38.57 180 bottom
PL308  -  [MURAT_BLM18SG700TN1D_2P]  167.33 25.07 90 bottom
PL309  -  [CYNTE_PCME051E-2R2MS_2P]  201.72 29.15 180 bottom
PL310  -  [MURAT_BLM18SG700TN1D_2P]  201.24 36.36 90 top
PL401  -  [CYNTE_PHI25201B-2R2MS_2P]  112.14 81.34 90 bottom
PL402  -  [CYNTE_PHI25201B-2R2MS_2P]  203 68.16 90 bottom
PL501  -  [KC_FBMA-L11-201209-221LMA30_2P]  149.26 80.58 180 bottom
PL502  -  [CYNTE_PCMB063T-2R2MS_2P]  134.15 81.8 180 bottom
PL601  -  [KC_FBMA-L11-201209-221LMA30_2P]  85.12 20.8 90 bottom
PL602  -  [CYNTE_PCMB063T-2R2MS_2P]  56.45 21.93 180 bottom
PL701  -  [TOKO_FDUM0640J-H-R36M-P3_4P]  30.94 68.3 270 bottom
PL702  -  [TOKO_FDUM0640J-H-R36M-P3_4P]  23.35 68.3 270 bottom
PL703  -  [KC_FBMA-L11-201209-221LMA30_2P]  37.29 78.47 180 bottom
PQ101  -  [FDV301N_NL_SOT23-3]  185.59 76.57 180 top
PQ102  -  [RHU002N06_SOT323-3]  190.74 76.01 90 top
PQ103  -  [2N7002KDWH_SOT363-6]  136.31 46.15 0 top
PQ104  -  [SSM3K7002FU_SC70-3]  117.28 24.92 0 top
PQ105  -  [2N7002KDWH_SOT363-6]  113.83 25.7 0 top
PQ106  -  [SSM3K7002FU_SC70-3]  114.77 55.38 0 top
PQ201  -  [CSD87312Q3E_SON8-4]  170.34 41.14 180 top
PQ202  -  [SSM3K7002FU_SC70-3]  140.66 48.45 270 top
PQ203  -  [SIR472DP-T1-GE3_POWERPAK8-5]  156.65 38.44 0 top
PQ204  -  [SSM3K7002FU_SC70-3]  143.52 38.19 270 top
PQ205  -  [SI7716ADN-T1-GE3_POWERPAK8-5]  157.04 35.9 270 top
PQ206  -  [AO4407AL_SO8]  138.1 35.64 270 bottom
PQ300  -  [SSM3K7002FU_SC70-3]  208.82 34.52 270 bottom
PQ601  -  [AON7406L_DFN8-5]  50.58 24.6 270 top
PQ602  -  [AON7212L_DFN8-5]  50.6 19.14 90 top
PR102  -  [R_0402]  195.07 78.46 180 top
PR103  -  [R_0402]  191.32 78.07 0 top
PR104  -  [R_0402]  191.92 75.96 270 top
PR105  -  [R_0402]  188.81 78.42 90 top
PR106  -  [R_0402]  189.69 79.34 270 top
PR107  -  [R_0402]  191.32 77.14 0 top
PR108  -  [R_0402]  118.04 27.95 90 top
PR109  -  [R_0402]  127.53 29.04 180 top
PR110  -  [R_0402]  114.49 59.34 0 top
PR111  -  [R_0402]  124.71 29.04 0 top
PR112  -  [R_0402]  123.58 29.04 180 top
PR113  -  [R_0402]  121.67 29.04 180 top
PR115  -  [R_0402]  119.45 25.54 90 top
PR116  -  [R_0402]  142.53 52.59 90 top
PR117  -  [R_0402]  147.56 62.37 0 top
PR118  -  [R_0402]  142.3 50.69 90 top
PR119  -  [R_0402]  136.6 44.08 90 top
PR120  -  [R_0402]  138.97 48.02 270 top
PR121  -  [R_0402]  137.48 50.2 270 top
PR122  -  [R_1206]  139.63 40.97 90 top
PR123  -  [R_0402]  115.3 24.47 0 top
PR124  -  [R_0402]  115.82 28.54 0 top
PR125  -  [R_0402]  113.52 24.47 0 top
PR126  -  [R_0402]  112.47 27.44 90 top
PR201  -  [R_1206_4P-D]  166.03 36.28 0 top
PR202  -  [R_0603]  167.47 38.15 90 top
PR203  -  [R_0402]  166.66 41.49 270 top
PR206  -  [R_0402]  167.6 42.51 180 top
PR208  -  [R_0402]  146.37 47.79 270 top
PR209  -  [R_1206]  141.8 43.84 90 top
PR210  -  [R_1206]  143.96 40.28 90 top
PR211  -  [R_0603]  152.48 42.74 0 top
PR213  -  [R_0402]  145.49 46.88 90 top
PR216  -  [R_1206_4P-D]  140.81 39.46 0 bottom
PR220  -  [R_1206]  154.74 36.47 90 top
PR223  -  [R_0402]  148.36 47.76 270 top
PR224  -  [R_0402]  145.85 41.03 90 top
PR225  -  [R_0402]  147.5 40.11 270 top
PR226  -  [R_0402]  147.26 46.88 90 top
PR230  -  [R_0402]  135.11 30.51 0 bottom
PR301  -  [R_0402]  210 34.53 90 bottom
PR304  -  [R_1206]  213.38 26.03 90 top
PR305  -  [R_0402]  211.5 31.39 270 top
PR306  -  [R_0402]  209.49 30.48 90 top
PR307  -  [R_0402]  212.47 30.48 90 top
PR308  -  [R_0402]  213.41 31.39 270 top
PR314  -  [R_1206]  203.49 51.43 90 bottom
PR315  -  [R_0402]  203.87 54.5 270 top
PR316  -  [R_0402]  201.91 53.58 90 top
PR317  -  [R_0402]  202.93 53.58 90 top
PR318  -  [R_0402]  205.66 52.72 270 top
PR324  -  [R_1206]  207.58 56.86 180 top
PR325  -  [R_0402]  208.92 62.32 180 top
PR326  -  [R_0402]  208.01 64.1 0 top
PR327  -  [R_0402]  208.01 61.43 0 top
PR328  -  [R_0402]  208.92 60.54 180 top
PR334  -  [R_1206]  177.71 37.46 90 bottom
PR335  -  [R_0402]  176.08 34.58 270 bottom
PR336  -  [R_0402]  177.85 33.68 90 bottom
PR337  -  [R_0402]  175.19 33.67 90 bottom
PR338  -  [R_0402]  176.16 35.52 180 bottom
PR341  -  [R_0402]  196.59 32.55 0 top
PR342  -  [R_0402]  196.59 34.05 0 top
PR344  -  [R_1206]  204.44 29.02 0 bottom
PR345  -  [R_0402]  208.52 34.37 180 top
PR346  -  [R_0402]  207.6 35.26 0 top
PR347  -  [R_0402]  207.6 32.59 0 top
PR348  -  [R_0402]  208.52 31.7 180 top
PR406  -  [R_1206]  112.25 80.02 270 bottom
PR407  -  [R_0402]  111.89 83.08 270 top
PR408  -  [R_0402]  110.98 82.16 180 top
PR411  -  [R_0402]  118.75 82.37 0 bottom
PR418  -  [R_1206]  203.02 66.83 270 bottom
PR419  -  [R_0402]  204.27 72.1 270 bottom
PR420  -  [R_0402]  205.16 71.21 90 bottom
PR424  -  [R_0402]  206.05 71.21 90 bottom
PR501  -  [R_0402]  135.68 74.71 0 bottom
PR503  -  [R_0402]  138.35 74.71 180 bottom
PR505  -  [R_0402]  142.37 77.95 270 bottom
PR506  -  [R_0603]  134.5 76.42 180 bottom
PR507  -  [R_1206]  131.53 77.61 270 bottom
PR508  -  [R_0402]  144.14 76.9 180 bottom
PR509  -  [R_0402]  134.27 74.23 180 bottom
PR601  -  [R_0603]  39.82 24.47 270 bottom
PR604  -  [R_0402]  43.35 21.55 90 top
PR605  -  [R_1206]  48.09 19.77 180 bottom
PR606  -  [R_0603]  45.66 22.68 270 top
PR608  -  [R_0402]  36.14 20.08 90 top
PR610  -  [R_0402]  37.09 19.14 180 top
PR611  -  [R_0402]  42.31 19.27 180 bottom
PR613  -  [R_0402]  42.31 20.15 180 bottom
PR615  -  [R_0402]  38.81 19.19 90 bottom
PR701  -  [R_0402]  29.16 84.2 270 bottom
PR702  -  [R_0402]  26.27 57.26 270 bottom
PR703  -  [R_0402]  29.48 75.35 270 top
PR704  -  [R_0402]  27.5 75.35 270 top
PR705  -  [R_0402]  24.7 75.35 270 top
PR706  -  [R_0402]  22.92 75.35 270 top
PR707  -  [R_0402]  27.13 57.26 270 bottom
PR708  -  [R_0402]  28.02 57.26 270 bottom
PR709  -  [R_0402]  31.3 74.43 90 top
PR710  -  [R_0402]  28.51 74.43 90 top
PR711  -  [R_0402]  26.63 74.65 90 top
PR712  -  [R_0402]  25.66 74.65 90 top
PR713  -  [R_0402]  23.81 74.43 90 top
PR714  -  [R_0402]  28.14 83.29 90 bottom
PR715  -  [R_0603]  37.66 76.15 0 bottom
PR717  -  [R_0402]  32.19 74.43 90 top
PR718  -  [R_0402]  36.42 78.22 180 top
PR719  -  [R_1206]  32.56 68.08 90 top
PR720  -  [R_0402]  34.65 78.22 180 top
PR721  -  [R_0402]  24.22 79.87 180 top
PR723  -  [R_0402]  24.22 80.81 180 top
PR724  -  [R_0402]  20.89 56.5 270 bottom
PR725  -  [R_0603]  22.87 81.95 0 top
PR726  -  [R_0402]  30.67 83.45 180 top
PR727  -  [R_0402]  29.76 84.34 0 top
PR728  -  [R_0402]  20 56.5 270 bottom
PR729  -  [R_0402]  19.11 56.5 270 bottom
PR730  -  [R_0603]  30.46 74.33 270 bottom
PR731  -  [R_0603]  26.11 83.48 90 top
PR733  -  [R_0402]  24.8 78.33 180 top
PR734  -  [R_1206]  21.95 68.29 90 top
PR735  -  [R_0402]  26.11 84.96 270 bottom
PR736  -  [R_0402]  24.67 84.26 270 bottom
PR737  -  [R_0402]  23.65 84.26 270 bottom
PR738  -  [R_0402]  23.05 78.33 180 top
PR744  -  [R_0402]  31.79 83.1 0 top
PR746  -  [R_0402]  32.04 81.62 270 top
PU201  -  [BQ24715RGRR_QFN20_3P5X3P5]  150.21 45.17 180 top
PU301  -  [TPS62130RGTR_QFN16_3X3]  211.45 26.75 90 top
PU302  -  [TPS62130RGTR_QFN16_3X3]  204.24 49.69 90 top
PU303  -  [TPS62130RGTR_QFN16_3X3]  204.4 61.56 0 top
PU304  -  [TPS62130RGTR_QFN16_3X3]  171.27 34.85 0 bottom
PU305  -  [TPS62130RGTR_QFN16_3X3]  203.63 30.97 0 top
PU306  -  [G920AT24U_SOT89-3]  185.1 27.8 90 bottom
PU307  -  [SN74AHC1G32DCKR_SC70-5]  210.56 49.71 90 top
PU401  -  [TPS62150RGTR_QFN16_3X3]  114.37 79.65 90 bottom
PU402  -  [TPS62140RGTR_QFN16_3X3]  205.16 67.27 90 bottom
PU501  -  [TPS51362RVER_QFN28_4P5X3P5]  137.02 76.94 90 bottom
PU601  -  [RT8207MZQW_WQFN20_3X3]  38.69 21.97 270 top
PU701  -  [TPS51622RSM_QFN32_4X4]  26.28 81.12 270 top
PU702  -  [CSD97374CQ4M_SON8_3P5X4P5-S]  38.06 71.16 180 bottom
PU703  -  [CSD97374CQ4M_SON8_3P5X4P5-S]  28.89 71.08 180 bottom
Q4  -  [SSM3K7002FU_SC70-3]  107.08 68.59 270 top
Q5  -  [SSM3K7002FU_SC70-3]  119.59 54.5 270 top
Q34  -  [SSM3K7002FU_SC70-3]  114.67 45.05 90 top
Q39  -  [SSM3K7002FU_SC70-3]  115.34 75.53 270 top
Q70  -  [SI3457BDV-T1-E3_TSOP6]  164.82 77.87 90 top
Q71  -  [SSM3K7002FU_SC70-3]  161.54 85.05 90 top
Q305  -  [SSM3K7002FU_SC70-3]  167.7 79.21 270 top
Q311  -  [SSM3K7002FU_SC70-3]  176.58 28.41 0 top
Q316  -  [DMN66D0LDW-7_SOT363-6]  226.06 8.1 270 top
Q318  -  [DMN66D0LDW-7_SOT363-6]  226.06 10.64 270 top
Q320  -  [DMN66D0LDW-7_SOT363-6]  226.06 5.56 270 top
Q326  -  [SSM3K7002FU_SC70-3]  174.68 26.57 180 top
Q329  -  [AO3419L_SOT23-3]  172.9 28.79 0 top
Q344  -  [SSM3K7002FU_SC70-3]  195.99 37.17 90 top
Q346  -  [SSM3K7002FU_SC70-3]  199.32 37.21 90 top
Q347  -  [MMBT3904_SOT23-3]  175.33 63.36 0 top
Q349  -  [DMN66D0LDW-7_SOT363-6]  169.7 47.07 0 top
Q351  -  [SSM3K7002FU_SC70-3]  91.6 48.98 270 top
Q352  -  [DMN66D0LDW-7_SOT363-6]  149.95 72.79 180 top
Q354  -  [AO3419L_SOT23-3]  216.34 24.22 90 bottom
Q355  -  [AO3419L_SOT23-3]  223.24 26.5 270 bottom
Q356  -  [AO3419L_SOT23-3]  223.24 22.44 270 bottom
Q357  -  [AO3419L_SOT23-3]  223.22 26.5 90 top
Q358  -  [AO3419L_SOT23-3]  223.22 22.44 90 top
Q359  -  [DMN66D0LDW-7_SOT363-6]  116.65 52.54 0 top
Q360  -  [SIS412DN-T1-GE3_POWERPAK8-5]  110.13 73.37 180 top
Q361  -  [SI1553CDL-T1-GE3_SC70-6]  117.18 77.37 90 top
Q362  -  [SSM3K7002FU_SC70-3]  115.33 72.11 270 top
Q363  -  [SSM3K7002FU_SC70-3]  169.04 76.14 270 bottom
Q364  -  [SSM3K7002FU_SC70-3]  136.07 28.85 270 bottom
QC5  -  [SSM3K7002FU_SC70-3]  110.45 79.5 270 top
QH3  -  [DMN66D0LDW-7_SOT363-6]  122.42 62.43 90 top
QH4  -  [DMN66D0LDW-7_SOT363-6]  125.72 62.43 90 top
QV2  -  [BSS138-G_SOT23-3]  214.66 62.94 90 top
R216  -  [R0603_0OHM]  133.47 51.65 0 top
R219  -  [R_0402]  147.68 50.38 0 top
R221  -  [R_0402]  138.44 54.07 270 top
R222  -  [R_0402]  212.45 33.99 0 top
R225  -  [R_0402]  146.78 49.49 90 top
R228  -  [R0402_0OHM]  148.98 53.94 180 top
R229  -  [R_0402]  148.19 54.9 0 top
R230  -  [R_0402]  148.19 55.79 0 top
R240  -  [R_0402]  148.42 65.07 90 top
R241  -  [R_0402]  148.06 53.05 0 top
R249  -  [R0402_0OHM]  136.38 59.91 0 top
R250  -  [R_0402]  136.35 56.3 0 top
R253  -  [R0402_0OHM]  145.18 67.82 270 top
R262  -  [R_0402]  212.45 32.97 0 top
R265  -  [R0402_0OHM]  30.65 83.31 90 bottom
R296  -  [R_0402]  115.88 46.01 270 top
R297  -  [R_0402]  107.69 65.67 90 top
R298  -  [R_0402]  118.09 55.4 0 top
R300  -  [R_0402]  112.28 74.6 0 top
R531  -  [R_0603]  158.1 83.06 270 top
R535  -  [R_0402]  164.9 85.27 270 top
R536  -  [R_0402]  162.87 84.36 90 top
